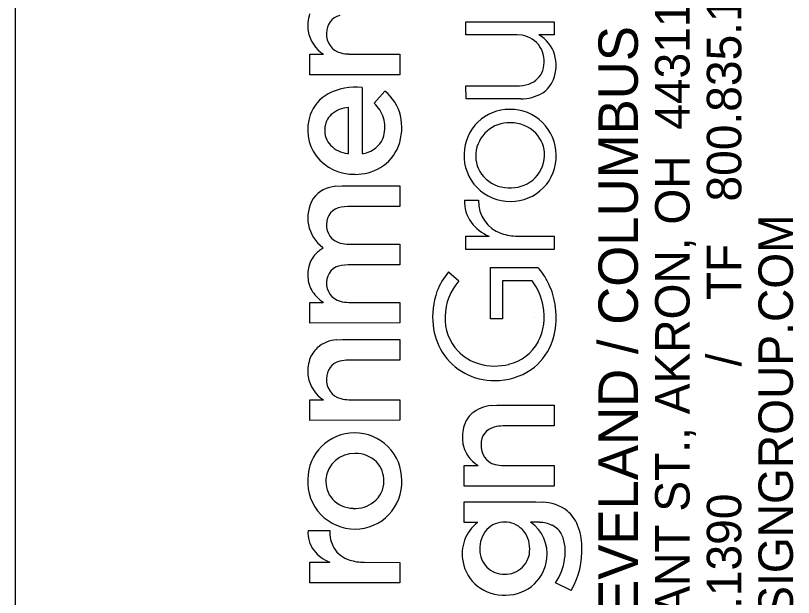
# Model space of a CAD drawing. Extents: x -0.4 to 34, y 0 to 22.
# Drawn here: x 32 to 33.125, y 3.095 to 3.936 of the extents above; entities that cross this region are included whole.
import ezdxf

# ---------------------------------------------------------------- set-up
doc = ezdxf.new("R2010")
doc.units = 0
doc.layers.add('DR_P_Erosion_Control', color=7, linetype='Continuous')
doc.layers.add('GK_Drainage_Nodes', color=7, linetype='Continuous')

msp = doc.modelspace()

# ---------------------------------------------------------------- linework, layer by layer
at = {"layer": 'DR_P_Erosion_Control'}
msp.add_line((32, 0.5), (32, 21.5), dxfattribs=at)
at = {"layer": 'GK_Drainage_Nodes'}
for p, q in [((32.6515, 3.908), (32.6515, 3.9267)), ((32.6515, 3.9267), (32.7791, 3.9266)), ((32.7791, 3.9266), (32.7791, 3.908)), ((32.7249, 3.908), (32.6515, 3.908)), ((32.7328, 3.9073), (32.7249, 3.908)), ((32.7791, 3.908), (32.7569, 3.908)), ((32.4254, 3.8503), (32.4254, 3.8802)), ((32.4254, 3.8802), (32.4455, 3.8802)), ((32.4822, 3.8802), (32.5557, 3.8802)), ((32.5557, 3.8802), (32.5557, 3.8504)), ((32.5557, 3.8504), (32.4254, 3.8503)), ((32.5011, 3.8321), (32.5012, 3.7366)), ((32.5188, 3.8093), (32.5342, 3.8266)), ((32.6515, 3.8344), (32.7291, 3.8345)), ((32.6517, 3.8154), (32.6515, 3.8344)), ((32.7307, 3.8154), (32.6517, 3.8154)), ((32.4814, 3.7364), (32.4814, 3.803)), ((32.4802, 3.7363), (32.4814, 3.7364)), ((32.4633, 3.6891), (32.4726, 3.6897)), ((32.4726, 3.6897), (32.5556, 3.6897)), ((32.5556, 3.6897), (32.5557, 3.6598)), ((32.6493, 3.6691), (32.6698, 3.6691)), ((32.4806, 3.6598), (32.471, 3.6588)), ((32.5557, 3.6598), (32.4806, 3.6598)), ((32.6515, 3.598), (32.6515, 3.617)), ((32.6515, 3.617), (32.6848, 3.617)), ((32.726, 3.617), (32.7791, 3.617)), ((32.7791, 3.617), (32.779, 3.598)), ((32.4444, 3.5992), (32.4446, 3.6007)), ((32.4822, 3.6055), (32.5557, 3.6055)), ((32.5557, 3.6055), (32.5557, 3.5757)), ((32.779, 3.598), (32.6515, 3.598)), ((32.4809, 3.5757), (32.4714, 3.5747)), ((32.5557, 3.5757), (32.4809, 3.5757)), ((32.6868, 3.5718), (32.7552, 3.5719)), ((32.6868, 3.4978), (32.6868, 3.5718)), ((32.6264, 3.5655), (32.6411, 3.5524)), ((32.7045, 3.5524), (32.7043, 3.4978)), ((32.7474, 3.5523), (32.7045, 3.5524)), ((32.4254, 3.4915), (32.4254, 3.5214)), ((32.4254, 3.5214), (32.4451, 3.5214)), ((32.4821, 3.5214), (32.5557, 3.5214)), ((32.5557, 3.5214), (32.5557, 3.4916)), ((32.75, 3.5), (32.75, 3.5)), ((32.5557, 3.4916), (32.4254, 3.4915)), ((32.7043, 3.4978), (32.6868, 3.4978)), ((32.4644, 3.4674), (32.4729, 3.4678)), ((32.4729, 3.4678), (32.5557, 3.4678)), ((32.5557, 3.4678), (32.5557, 3.438)), ((32.5557, 3.438), (32.4814, 3.438)), ((32.4254, 3.3509), (32.4254, 3.3807)), ((32.4254, 3.3807), (32.4455, 3.3807)), ((32.4822, 3.3807), (32.5557, 3.3807)), ((32.5557, 3.3807), (32.5557, 3.351)), ((32.6878, 3.3722), (32.6963, 3.3727)), ((32.6963, 3.3727), (32.7792, 3.3727)), ((32.7792, 3.3727), (32.7792, 3.3429)), ((32.5557, 3.351), (32.4254, 3.3509)), ((32.7792, 3.3429), (32.7048, 3.3428)), ((32.6489, 3.2557), (32.6489, 3.2855)), ((32.6489, 3.2855), (32.669, 3.2855)), ((32.7057, 3.2855), (32.7791, 3.2855)), ((32.7791, 3.2855), (32.7792, 3.2558)), ((32.7792, 3.2558), (32.6489, 3.2557)), ((32.6489, 3.2034), (32.6489, 3.2332)), ((32.6489, 3.2332), (32.7524, 3.2332)), ((32.7524, 3.2332), (32.7619, 3.2329)), ((32.6684, 3.2034), (32.6489, 3.2034)), ((32.7576, 3.2036), (32.7449, 3.2036)), ((32.423, 3.1919), (32.4545, 3.1919)), ((32.4254, 3.1159), (32.4254, 3.1458)), ((32.4254, 3.1458), (32.4547, 3.1458)), ((32.5041, 3.1458), (32.5557, 3.1457)), ((32.5557, 3.1457), (32.5556, 3.1159)), ((32.5556, 3.1159), (32.4254, 3.1159)), ((32.8036, 3.1049), (32.7812, 3.116))]:
    msp.add_line(p, q, dxfattribs=at)
for points in [[(32.7328, 3.9073), (32.7249, 3.908), (32.6515, 3.908), (32.6515, 3.9267), (32.7791, 3.9266), (32.7791, 3.908), (32.7569, 3.908)], [(32.4254, 3.8503), (32.4254, 3.8802), (32.4455, 3.8802)], [(32.4822, 3.8802), (32.5557, 3.8802), (32.5557, 3.8504), (32.4254, 3.8503)], [(32.5011, 3.8321), (32.5012, 3.7366)], [(32.5188, 3.8093), (32.5342, 3.8266)], [(32.7307, 3.8154), (32.6517, 3.8154), (32.6515, 3.8344), (32.7291, 3.8345)], [(32.4802, 3.7363), (32.4814, 3.7364), (32.4814, 3.803)], [(32.4633, 3.6891), (32.4726, 3.6897), (32.5556, 3.6897), (32.5557, 3.6598), (32.4806, 3.6598), (32.471, 3.6588)], [(32.6493, 3.6691), (32.6698, 3.6691)], [(32.6515, 3.598), (32.6515, 3.617), (32.6848, 3.617)], [(32.726, 3.617), (32.7791, 3.617), (32.779, 3.598), (32.6515, 3.598)], [(32.4444, 3.5992), (32.4446, 3.6007)], [(32.4822, 3.6055), (32.5557, 3.6055), (32.5557, 3.5757), (32.4809, 3.5757), (32.4714, 3.5747)], [(32.7474, 3.5523), (32.7045, 3.5524), (32.7043, 3.4978), (32.6868, 3.4978), (32.6868, 3.5718), (32.7552, 3.5719)], [(32.6264, 3.5655), (32.6411, 3.5524)], [(32.4254, 3.4915), (32.4254, 3.5214), (32.4451, 3.5214)], [(32.4821, 3.5214), (32.5557, 3.5214), (32.5557, 3.4916), (32.4254, 3.4915)], [(32.4644, 3.4674), (32.4729, 3.4678), (32.5557, 3.4678), (32.5557, 3.438), (32.4814, 3.438)], [(32.4254, 3.3509), (32.4254, 3.3807), (32.4455, 3.3807)], [(32.4822, 3.3807), (32.5557, 3.3807), (32.5557, 3.351), (32.4254, 3.3509)], [(32.6878, 3.3722), (32.6963, 3.3727), (32.7792, 3.3727), (32.7792, 3.3429), (32.7048, 3.3428)], [(32.6489, 3.2557), (32.6489, 3.2855), (32.669, 3.2855)], [(32.7057, 3.2855), (32.7791, 3.2855), (32.7792, 3.2558), (32.6489, 3.2557)], [(32.6684, 3.2034), (32.6489, 3.2034), (32.6489, 3.2332), (32.7524, 3.2332), (32.7619, 3.2329)], [(32.7576, 3.2036), (32.7449, 3.2036)], [(32.423, 3.1919), (32.4545, 3.1919)], [(32.4254, 3.1159), (32.4254, 3.1458), (32.4547, 3.1458)], [(32.5041, 3.1458), (32.5557, 3.1457), (32.5556, 3.1159), (32.4254, 3.1159)], [(32.8036, 3.1049), (32.7812, 3.116)]]:
    msp.add_lwpolyline(points, dxfattribs=at)
for centre, radius, start, end in [((32.4787, 3.9211), 0.056, 162.274, 187.7917), ((32.4787, 3.9211), 0.056, 162.274, 187.7917), ((32.4748, 3.9116), 0.025, 103.6868, 182.214), ((32.4748, 3.9116), 0.025, 103.6868, 182.214), ((32.4703, 3.9209), 0.0476, 188.9646, 238.6987), ((32.4703, 3.9209), 0.0476, 188.9646, 238.6987), ((32.4774, 3.9085), 0.0276, 175.5844, 255.1382), ((32.4774, 3.9085), 0.0276, 175.5844, 255.1382), ((32.7271, 3.87), 0.0377, 33.5008, 81.3295), ((32.7271, 3.87), 0.0377, 33.5008, 81.3295), ((32.7324, 3.8648), 0.0496, 17.6221, 60.3897), ((32.7324, 3.8648), 0.0496, 17.6221, 60.3897), ((32.4818, 3.9224), 0.0421, 254.0891, 270.5284), ((32.4818, 3.9224), 0.0421, 254.0891, 270.5284), ((32.7241, 3.8695), 0.0405, 346.5618, 31.7539), ((32.7241, 3.8695), 0.0405, 346.5618, 31.7539), ((32.7234, 3.8641), 0.0584, 339.162, 15.6148), ((32.7234, 3.8641), 0.0584, 339.162, 15.6148), ((32.7337, 3.8662), 0.0304, 294.6321, 348.4863), ((32.7337, 3.8662), 0.0304, 294.6321, 348.4863), ((32.7275, 3.8808), 0.0463, 271.952, 294.0894), ((32.7275, 3.8808), 0.0463, 271.952, 294.0894), ((32.739, 3.859), 0.042, 303.1039, 338.1561), ((32.739, 3.859), 0.042, 303.1039, 338.1561), ((32.4918, 3.7487), 0.0839, 83.6212, 118.2845), ((32.4918, 3.7487), 0.0839, 83.6212, 118.2845), ((32.494, 3.7763), 0.0644, 13.5328, 51.3627), ((32.494, 3.7763), 0.0644, 13.5328, 51.3627), ((32.4789, 3.7737), 0.0558, 118.8294, 160.6224), ((32.4789, 3.7737), 0.0558, 118.8294, 160.6224), ((32.7321, 3.8726), 0.0571, 268.627, 301.4778), ((32.7321, 3.8726), 0.0571, 268.627, 301.4778), ((32.4844, 3.7607), 0.0424, 94.0131, 130.8806), ((32.4844, 3.7607), 0.0424, 94.0131, 130.8806), ((32.4803, 3.7702), 0.0549, 19.0387, 45.4432), ((32.4803, 3.7702), 0.0549, 19.0387, 45.4432), ((32.487, 3.7707), 0.0644, 160.5214, 215.7815), ((32.487, 3.7707), 0.0644, 160.5214, 215.7815), ((32.477, 3.7709), 0.0298, 132.9855, 177.1802), ((32.477, 3.7709), 0.0298, 132.9855, 177.1802), ((32.7143, 3.7348), 0.0655, 89.4821, 178.7775), ((32.7143, 3.7348), 0.0655, 89.4821, 178.7775), ((32.7158, 3.7341), 0.0662, 0.4227, 90.7613), ((32.7158, 3.7341), 0.0662, 0.4227, 90.7613), ((32.4872, 3.7743), 0.047, 344.6072, 17.0067), ((32.4872, 3.7743), 0.047, 344.6072, 17.0067), ((32.4829, 3.7738), 0.0758, 339.3543, 13.3771), ((32.4829, 3.7738), 0.0758, 339.3543, 13.3771), ((32.714, 3.7324), 0.0485, 87.6883, 175.017), ((32.714, 3.7324), 0.0485, 87.6883, 175.017), ((32.7166, 3.7304), 0.0505, 44.912, 90.7591), ((32.7166, 3.7304), 0.0505, 44.912, 90.7591), ((32.4782, 3.7697), 0.0311, 175.0014, 223.2876), ((32.4782, 3.7697), 0.0311, 175.0014, 223.2876), ((32.499, 3.7718), 0.035, 288.0108, 343.5536), ((32.499, 3.7718), 0.035, 288.0108, 343.5536), ((32.7196, 3.7345), 0.0455, 358.3228, 43.8349), ((32.7196, 3.7345), 0.0455, 358.3228, 43.8349), ((32.4855, 3.7783), 0.0423, 225.0645, 262.797), ((32.4855, 3.7783), 0.0423, 225.0645, 262.797), ((32.4955, 3.7698), 0.0626, 300.9439, 338.7322), ((32.4955, 3.7698), 0.0626, 300.9439, 338.7322), ((32.5013, 3.7568), 0.0202, 269.7004, 294.8729), ((32.5013, 3.7568), 0.0202, 269.7004, 294.8729), ((32.7148, 3.7334), 0.0661, 177.5373, 270.9452), ((32.7148, 3.7334), 0.0661, 177.5373, 270.9452), ((32.7108, 3.7331), 0.0453, 175.5147, 221.4205), ((32.7108, 3.7331), 0.0453, 175.5147, 221.4205), ((32.4891, 3.7752), 0.0687, 217.7434, 271.6561), ((32.4891, 3.7752), 0.0687, 217.7434, 271.6561), ((32.7167, 3.7327), 0.0654, 269.3083, 1.6791), ((32.7167, 3.7327), 0.0654, 269.3083, 1.6791), ((32.7193, 3.7337), 0.0457, 308.9038, 359.3095), ((32.7193, 3.7337), 0.0457, 308.9038, 359.3095), ((32.492, 3.777), 0.0706, 269.2053, 300.3357), ((32.492, 3.777), 0.0706, 269.2053, 300.3357), ((32.714, 3.7373), 0.0505, 222.6626, 268.3733), ((32.714, 3.7373), 0.0505, 222.6626, 268.3733), ((32.7157, 3.7386), 0.0518, 266.5531, 308.6725), ((32.7157, 3.7386), 0.0518, 266.5531, 308.6725), ((32.4664, 3.644), 0.0452, 93.9112, 142.3072), ((32.4664, 3.644), 0.0452, 93.9112, 142.3072), ((32.4759, 3.6437), 0.0532, 148.2879, 233.9556), ((32.4759, 3.6437), 0.0532, 148.2879, 233.9556), ((32.6988, 3.6666), 0.0495, 177.1621, 216.2802), ((32.6988, 3.6666), 0.0495, 177.1621, 216.2802), ((32.7173, 3.6664), 0.0476, 176.7699, 252.1504), ((32.7173, 3.6664), 0.0476, 176.7699, 252.1504), ((32.4738, 3.635), 0.024, 96.7576, 181.6251), ((32.4738, 3.635), 0.024, 96.7576, 181.6251), ((32.4758, 3.6324), 0.026, 175.8157, 256.1672), ((32.4758, 3.6324), 0.026, 175.8157, 256.1672), ((32.7098, 3.6755), 0.0637, 216.9153, 246.8862), ((32.7098, 3.6755), 0.0637, 216.9153, 246.8862), ((32.7269, 3.6917), 0.0747, 251.1388, 269.3469), ((32.7269, 3.6917), 0.0747, 251.1388, 269.3469), ((32.4817, 3.6505), 0.045, 254.3463, 270.6103), ((32.4817, 3.6505), 0.045, 254.3463, 270.6103), ((32.4619, 3.5645), 0.0387, 139.5245, 154.847), ((32.4619, 3.5645), 0.0387, 139.5245, 154.847), ((32.4638, 3.5627), 0.0414, 117.9163, 139.243), ((32.4638, 3.5627), 0.0414, 117.9163, 139.243), ((32.4714, 3.5612), 0.0488, 156.0638, 187.3493), ((32.4714, 3.5612), 0.0488, 156.0638, 187.3493), ((32.4742, 3.5506), 0.0243, 96.5532, 179.949), ((32.4742, 3.5506), 0.0243, 96.5532, 179.949), ((32.725, 3.5394), 0.0444, 30.9891, 47.161), ((32.725, 3.5394), 0.0444, 30.9891, 47.161), ((32.7016, 3.5019), 0.0986, 139.7948, 159.137), ((32.7016, 3.5019), 0.0986, 139.7948, 159.137), ((32.6709, 3.5002), 0.1111, 25.3031, 33.9618), ((32.6709, 3.5002), 0.1111, 25.3031, 33.9618), ((32.4646, 3.5597), 0.0418, 186.5579, 213.3885), ((32.4646, 3.5597), 0.0418, 186.5579, 213.3885), ((32.4761, 3.5486), 0.0263, 175.722, 255.7863), ((32.4761, 3.5486), 0.0263, 175.722, 255.7863), ((32.699, 3.5008), 0.0775, 138.258, 179.7006), ((32.699, 3.5008), 0.0775, 138.258, 179.7006), ((32.6789, 3.501), 0.0856, 10.0751, 36.8319), ((32.6789, 3.501), 0.0856, 10.0751, 36.8319), ((32.6704, 3.4999), 0.1117, 8.8034, 25.3348), ((32.6704, 3.4999), 0.1117, 8.8034, 25.3348), ((32.4789, 3.5708), 0.0598, 214.7043, 235.6872), ((32.4789, 3.5708), 0.0598, 214.7043, 235.6872), ((32.7187, 3.4997), 0.1154, 161.1438, 185.6281), ((32.7187, 3.4997), 0.1154, 161.1438, 185.6281), ((32.4819, 3.5652), 0.0438, 253.6672, 270.1498), ((32.4819, 3.5652), 0.0438, 253.6672, 270.1498), ((32.6842, 3.5006), 0.0804, 333.4669, 11.0367), ((32.6842, 3.5006), 0.0804, 333.4669, 11.0367), ((32.6756, 3.4998), 0.1065, 338.2887, 9.2855), ((32.6756, 3.4998), 0.1065, 338.2887, 9.2855), ((32.6881, 3.4973), 0.0668, 176.6658, 223.6912), ((32.6881, 3.4973), 0.0668, 176.6658, 223.6912), ((32.6934, 3.497), 0.0899, 185.5077, 212.0129), ((32.6934, 3.497), 0.0899, 185.5077, 212.0129), ((32.4687, 3.4177), 0.0499, 94.9706, 130.2248), ((32.4687, 3.4177), 0.0499, 94.9706, 130.2248), ((32.4635, 3.426), 0.0402, 132.2238, 161.6823), ((32.4635, 3.426), 0.0402, 132.2238, 161.6823), ((32.6987, 3.4955), 0.0652, 282.8815, 331.8147), ((32.6987, 3.4955), 0.0652, 282.8815, 331.8147), ((32.6984, 3.4917), 0.0824, 305.0306, 337.6757), ((32.6984, 3.4917), 0.0824, 305.0306, 337.6757), ((32.6921, 3.4975), 0.0891, 212.7022, 270.714), ((32.6921, 3.4975), 0.0891, 212.7022, 270.714), ((32.6905, 3.5001), 0.0704, 224.0215, 253.88), ((32.6905, 3.5001), 0.0704, 224.0215, 253.88), ((32.4787, 3.4216), 0.056, 162.274, 187.7917), ((32.4787, 3.4216), 0.056, 162.274, 187.7917), ((32.4748, 3.4121), 0.025, 103.6868, 182.214), ((32.4748, 3.4121), 0.025, 103.6868, 182.214), ((32.4811, 3.392), 0.046, 89.6051, 105.3303), ((32.4811, 3.392), 0.046, 89.6051, 105.3303), ((32.6932, 3.5125), 0.0831, 254.4535, 283.9512), ((32.6932, 3.5125), 0.0831, 254.4535, 283.9512), ((32.6943, 3.4998), 0.0914, 269.3273, 304.1963), ((32.6943, 3.4998), 0.0914, 269.3273, 304.1963), ((32.4703, 3.4214), 0.0476, 188.9646, 238.6987), ((32.4703, 3.4214), 0.0476, 188.9646, 238.6987), ((32.4774, 3.409), 0.0276, 175.5844, 255.1382), ((32.4774, 3.409), 0.0276, 175.5844, 255.1382), ((32.4818, 3.4229), 0.0421, 254.0891, 270.5284), ((32.4818, 3.4229), 0.0421, 254.0891, 270.5284), ((32.6922, 3.3225), 0.0499, 94.9706, 130.2248), ((32.6922, 3.3225), 0.0499, 94.9706, 130.2248), ((32.6869, 3.3309), 0.0402, 132.2238, 161.6823), ((32.6869, 3.3309), 0.0402, 132.2238, 161.6823), ((32.7022, 3.3264), 0.056, 162.274, 187.7917), ((32.7022, 3.3264), 0.056, 162.274, 187.7917), ((32.7045, 3.2968), 0.046, 89.6051, 105.3303), ((32.7045, 3.2968), 0.046, 89.6051, 105.3303), ((32.4901, 3.2654), 0.0674, 89.8476, 179.6405), ((32.4901, 3.2654), 0.0674, 89.8476, 179.6405), ((32.4906, 3.2647), 0.0681, 359.5401, 90.2114), ((32.4906, 3.2647), 0.0681, 359.5401, 90.2114), ((32.6983, 3.3169), 0.025, 103.6868, 182.214), ((32.6983, 3.3169), 0.025, 103.6868, 182.214), ((32.6937, 3.3262), 0.0476, 188.9646, 238.6987), ((32.6937, 3.3262), 0.0476, 188.9646, 238.6987), ((32.7008, 3.3138), 0.0276, 175.5844, 255.1382), ((32.7008, 3.3138), 0.0276, 175.5844, 255.1382), ((32.4892, 3.2626), 0.0404, 87.0481, 175.5726), ((32.4892, 3.2626), 0.0404, 87.0481, 175.5726), ((32.492, 3.26), 0.043, 45.8426, 90.9801), ((32.492, 3.26), 0.043, 45.8426, 90.9801), ((32.4946, 3.2642), 0.0382, 357.8857, 44.159), ((32.4946, 3.2642), 0.0382, 357.8857, 44.159), ((32.7053, 3.3277), 0.0421, 254.0891, 270.5284), ((32.7053, 3.3277), 0.0421, 254.0891, 270.5284), ((32.4908, 3.2621), 0.0682, 176.8344, 270.4038), ((32.4908, 3.2621), 0.0682, 176.8344, 270.4038), ((32.4873, 3.2625), 0.0385, 175.1538, 221.1471), ((32.4873, 3.2625), 0.0385, 175.1538, 221.1471), ((32.4912, 3.2614), 0.0675, 270.0624, 2.3776), ((32.4912, 3.2614), 0.0675, 270.0624, 2.3776), ((32.4945, 3.2632), 0.0383, 308.2894, 359.4347), ((32.4945, 3.2632), 0.0383, 308.2894, 359.4347), ((32.4892, 3.2661), 0.0423, 223.0999, 268.8089), ((32.4892, 3.2661), 0.0423, 223.0999, 268.8089), ((32.491, 3.2679), 0.0442, 266.5651, 308.0608), ((32.491, 3.2679), 0.0442, 266.5651, 308.0608), ((32.7591, 3.1679), 0.065, 53.4034, 87.4906), ((32.7591, 3.1679), 0.065, 53.4034, 87.4906), ((32.7652, 3.1804), 0.0514, 21.6075, 50.5577), ((32.7652, 3.1804), 0.0514, 21.6075, 50.5577), ((32.7029, 3.1581), 0.0569, 127.3748, 192.2247), ((32.7029, 3.1581), 0.0569, 127.3748, 192.2247), ((32.7069, 3.1693), 0.0346, 88.473, 136.4256), ((32.7069, 3.1693), 0.0346, 88.473, 136.4256), ((32.7081, 3.1696), 0.0342, 44.2719, 90.4762), ((32.7081, 3.1696), 0.0342, 44.2719, 90.4762), ((32.7142, 3.1583), 0.0547, 352.1125, 55.923), ((32.7142, 3.1583), 0.0547, 352.1125, 55.923), ((32.7567, 3.1572), 0.0463, 65.0169, 88.8011), ((32.7567, 3.1572), 0.0463, 65.0169, 88.8011), ((32.7626, 3.1716), 0.0309, 26.2681, 63.803), ((32.7626, 3.1716), 0.0309, 26.2681, 63.803), ((32.7307, 3.1671), 0.0884, 1.1514, 21.3627), ((32.7307, 3.1671), 0.0884, 1.1514, 21.3627), ((32.4662, 3.1888), 0.0433, 175.8731, 216.3475), ((32.4662, 3.1888), 0.0433, 175.8731, 216.3475), ((32.5009, 3.1895), 0.0464, 176.9688, 209.6064), ((32.5009, 3.1895), 0.0464, 176.9688, 209.6064), ((32.7114, 3.166), 0.0401, 137.4674, 182.3324), ((32.7114, 3.166), 0.0401, 137.4674, 182.3324), ((32.7037, 3.166), 0.04, 358.5714, 43.5376), ((32.7037, 3.166), 0.04, 358.5714, 43.5376), ((32.7357, 3.1615), 0.0595, 349.3073, 23.4307), ((32.7357, 3.1615), 0.0595, 349.3073, 23.4307), ((32.4747, 3.1972), 0.0551, 218.0981, 248.7907), ((32.4747, 3.1972), 0.0551, 218.0981, 248.7907), ((32.4951, 3.1881), 0.0408, 211.9447, 253.2028), ((32.4951, 3.1881), 0.0408, 211.9447, 253.2028), ((32.7065, 3.1637), 0.0351, 178.8821, 271.0837), ((32.7065, 3.1637), 0.0351, 178.8821, 271.0837), ((32.7082, 3.164), 0.0355, 268.2788, 1.5502), ((32.7082, 3.164), 0.0355, 268.2788, 1.5502), ((32.7054, 3.1624), 0.1138, 329.6388, 3.26), ((32.7054, 3.1624), 0.1138, 329.6388, 3.26), ((32.7099, 3.1571), 0.0589, 313.742, 353.8554), ((32.7099, 3.1571), 0.0589, 313.742, 353.8554), ((32.7074, 3.1633), 0.0877, 327.3149, 351.5748), ((32.7074, 3.1633), 0.0877, 327.3149, 351.5748), ((32.5047, 3.2165), 0.0707, 252.4655, 269.573), ((32.5047, 3.2165), 0.0707, 252.4655, 269.573), ((32.7046, 3.157), 0.0584, 190.7518, 231.2892), ((32.7046, 3.157), 0.0584, 190.7518, 231.2892), ((32.7063, 3.1611), 0.0627, 232.4606, 272.5902), ((32.7063, 3.1611), 0.0627, 232.4606, 272.5902), ((32.7095, 3.159), 0.0605, 269.6361, 312.7088), ((32.7095, 3.159), 0.0605, 269.6361, 312.7088)]:
    msp.add_arc(centre, radius, start, end, dxfattribs=at)

# ---------------------------------------------------------------- texts
for s, height, p in [('800.835.1390', 0.049846, (33.0497, 3.6671)), ('450 GRANT ST., AKRON, OH  44311', 0.049846, (32.9749, 2.8374)), ('AKRON / CLEVELAND / COLUMBUS', 0.056969, (32.9001, 2.638)), ('ENVDESIGNGROUP.COM', 0.049846, (33.1244, 2.8374)), ('TF', 0.04985, (33.0497, 3.5246)), ('/  ', 0.04985, (33.0497, 3.4288)), ('330.375.1390', 0.049846, (33.0497, 2.8374))]:
    msp.add_text(s, height=height, rotation=90, dxfattribs=at).set_placement(p)

doc.saveas('drawing.dxf')
